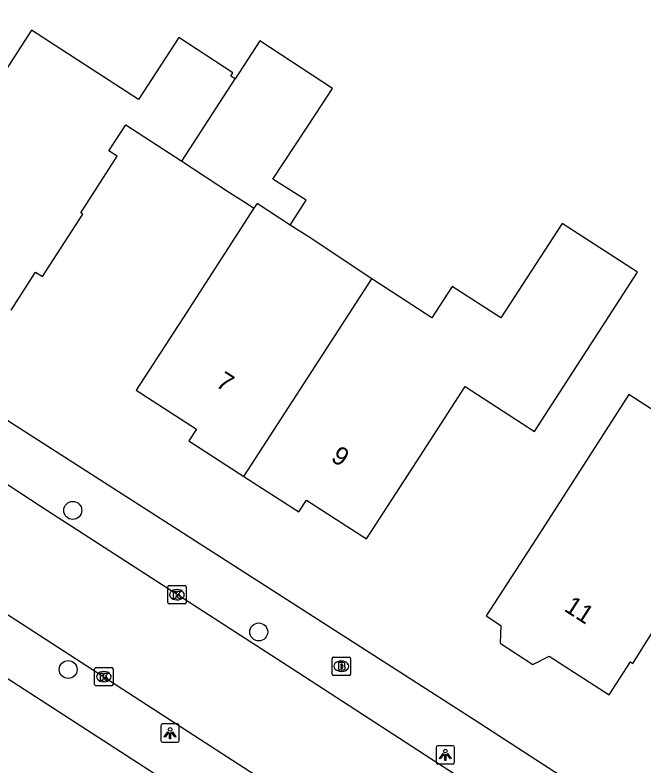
# Model space of a CAD drawing. Extents: x 161141 to 161601, y 381708 to 382245.
# Drawn here: x 161425.51 to 161459.73, y 382085.7 to 382126.58 of the extents above; entities that cross this region are included whole.
import ezdxf

# ---------------------------------------------------------------- set-up
doc = ezdxf.new("R2010")
doc.units = 0
for name, color, linetype in [('IMGEO_Boom', 7, 'Continuous'), ('IMGEO_Brandkraan', 7, 'Continuous'), ('IMGEO_Kolk', 7, 'Continuous'), ('IMGEO_Lichtpunt', 7, 'Continuous'), ('IMGEO_Pand', 7, 'Continuous'), ('IMGEO_Pand_nummerreeks', 7, 'Continuous'), ('IMGEO_Rijbaan_lokaal_open', 7, 'Continuous'), ('IMGEO_Voetpad_open', 7, 'Continuous')]:
    doc.layers.add(name, color=color, linetype=linetype)

msp = doc.modelspace()

# ---------------------------------------------------------------- linework, layer by layer
at = {"layer": 'IMGEO_Boom'}
for centre in [(161428.654, 382099.608), (161438.771, 382092.992), (161428.405, 382090.947)]:
    msp.add_circle(centre, 0.489, dxfattribs=at)
at = {"layer": 'IMGEO_Brandkraan'}
for p, q in [((161442.841, 382091.627), (161443.693, 382091.627)), ((161442.766, 382090.701), (161442.766, 382091.553)), ((161443.254, 382091.407), (161443.279, 382091.407)), ((161443.767, 382091.553), (161443.767, 382090.701)), ((161443.277, 382090.847), (161443.252, 382090.847)), ((161443.693, 382090.627), (161442.841, 382090.627))]:
    msp.add_line(p, q, dxfattribs=at)
for points in [[(161442.841, 382091.627), (161443.693, 382091.627)], [(161442.766, 382090.701), (161442.766, 382091.553)], [(161443.114, 382091.327), (161443.114, 382090.927), (161443.327, 382090.927)], [(161443.345, 382091.327), (161443.114, 382091.327)], [(161443.293, 382091.246), (161443.239, 382091.246), (161443.239, 382091.17)], [(161443.767, 382091.553), (161443.767, 382090.701)], [(161443.239, 382091.17), (161443.292, 382091.17)], [(161443.301, 382091.094), (161443.239, 382091.094), (161443.239, 382091.013)], [(161443.239, 382091.013), (161443.301, 382091.013)], [(161443.693, 382090.627), (161442.841, 382090.627)]]:
    msp.add_lwpolyline(points, dxfattribs=at)
for centre, radius, start, end in [((161442.843, 382091.551), 0.0765, 91.552, 178.448), ((161442.843, 382091.551), 0.0765, 91.552, 178.448), ((161443.691, 382091.551), 0.0765, 1.552, 88.448), ((161443.691, 382091.551), 0.0765, 1.552, 88.448), ((161443.294, 382091.208), 0.0379, 267.8285, 90.9355), ((161443.349, 382091.182), 0.145, 59.4692, 91.5367), ((161443.374, 382091.229), 0.0922, 285.5137, 58.1501), ((161443.302, 382091.053), 0.0404, 269.8759, 90.5077), ((161443.333, 382091.178), 0.251, 268.6676, 293.5347), ((161443.379, 382091.037), 0.105, 301.3115, 78.989), ((161442.843, 382090.703), 0.0765, 181.552, 268.448), ((161442.843, 382090.703), 0.0765, 181.552, 268.448), ((161443.691, 382090.703), 0.0765, 271.552, 358.448), ((161443.691, 382090.703), 0.0765, 271.552, 358.448)]:
    msp.add_arc(centre, radius, start, end, dxfattribs=at)
for centre, major_axis, ratio, start_param, end_param in [((161443.253, 382091.127), (-0.387, 0.002), 0.722429, 4.712389, 7.853982), ((161443.278, 382091.127), (-0.39, 0.002), 0.717154, 1.570796, 4.712389)]:
    msp.add_ellipse(centre, major_axis=major_axis, ratio=ratio, start_param=start_param, end_param=end_param, dxfattribs=at)
at = {"layer": 'IMGEO_Kolk'}
for p, q in [((161433.819, 382094.594), (161433.819, 382095.446)), ((161433.894, 382095.52), (161434.746, 382095.52)), ((161434.307, 382095.3), (161434.332, 382095.3)), ((161434.82, 382095.446), (161434.82, 382094.594)), ((161434.746, 382094.52), (161433.894, 382094.52)), ((161434.33, 382094.74), (161434.305, 382094.74)), ((161429.846, 382090.131), (161429.846, 382090.983)), ((161429.921, 382091.057), (161430.773, 382091.057)), ((161430.334, 382090.837), (161430.359, 382090.837)), ((161430.847, 382090.983), (161430.847, 382090.131)), ((161430.773, 382090.057), (161429.921, 382090.057)), ((161430.357, 382090.277), (161430.332, 382090.277))]:
    msp.add_line(p, q, dxfattribs=at)
for points in [[(161433.819, 382094.594), (161433.819, 382095.446)], [(161433.894, 382095.52), (161434.746, 382095.52)], [(161434.82, 382095.446), (161434.82, 382094.594)], [(161434.14, 382095.22), (161434.263, 382095.22), (161434.263, 382095.069), (161434.393, 382095.22), (161434.557, 382095.22), (161434.411, 382095.069), (161434.564, 382094.82), (161434.412, 382094.82), (161434.327, 382094.984), (161434.263, 382094.917), (161434.263, 382094.82), (161434.14, 382094.82), (161434.14, 382095.22)], [(161434.746, 382094.52), (161433.894, 382094.52)], [(161429.846, 382090.131), (161429.846, 382090.983)], [(161429.921, 382091.057), (161430.773, 382091.057)], [(161430.847, 382090.983), (161430.847, 382090.131)], [(161430.167, 382090.757), (161430.29, 382090.757), (161430.29, 382090.606), (161430.42, 382090.757), (161430.584, 382090.757), (161430.438, 382090.606), (161430.591, 382090.357), (161430.439, 382090.357), (161430.354, 382090.521), (161430.29, 382090.454), (161430.29, 382090.357), (161430.167, 382090.357), (161430.167, 382090.757)], [(161430.773, 382090.057), (161429.921, 382090.057)]]:
    msp.add_lwpolyline(points, dxfattribs=at)
for centre, start, end in [((161433.896, 382095.444), 91.552, 178.448), ((161433.896, 382095.444), 91.552, 178.448), ((161434.744, 382095.444), 1.552, 88.448), ((161434.744, 382095.444), 1.552, 88.448), ((161433.896, 382094.596), 181.552, 268.448), ((161433.896, 382094.596), 181.552, 268.448), ((161434.744, 382094.596), 271.552, 358.448), ((161434.744, 382094.596), 271.552, 358.448), ((161429.923, 382090.981), 91.552, 178.448), ((161429.923, 382090.981), 91.552, 178.448), ((161430.771, 382090.981), 1.552, 88.448), ((161430.771, 382090.981), 1.552, 88.448), ((161429.923, 382090.133), 181.552, 268.448), ((161429.923, 382090.133), 181.552, 268.448), ((161430.771, 382090.133), 271.552, 358.448), ((161430.771, 382090.133), 271.552, 358.448)]:
    msp.add_arc(centre, 0.0765, start, end, dxfattribs=at)
for centre, major_axis, ratio, start_param, end_param in [((161434.306, 382095.02), (-0.387, 0.002), 0.722429, 4.712389, 7.853982), ((161434.331, 382095.02), (-0.39, 0.002), 0.717154, 1.570796, 4.712389), ((161430.333, 382090.557), (-0.387, 0.002), 0.722429, 4.712389, 7.853982), ((161430.358, 382090.557), (-0.39, 0.002), 0.717154, 1.570796, 4.712389)]:
    msp.add_ellipse(centre, major_axis=major_axis, ratio=ratio, start_param=start_param, end_param=end_param, dxfattribs=at)
at = {"layer": 'IMGEO_Lichtpunt'}
for p, q in [((161434.35, 382087.983), (161433.542, 382087.983)), ((161434.35, 382087.983), (161433.542, 382087.983)), ((161433.448, 382087.888), (161433.448, 382087.081)), ((161433.448, 382087.888), (161433.448, 382087.081)), ((161434.444, 382087.081), (161434.444, 382087.888)), ((161434.444, 382087.081), (161434.444, 382087.888)), ((161433.542, 382086.987), (161434.35, 382086.987)), ((161433.542, 382086.987), (161434.35, 382086.987)), ((161448.424, 382086.706), (161448.424, 382085.899)), ((161448.424, 382086.706), (161448.424, 382085.899)), ((161449.326, 382086.801), (161448.518, 382086.801)), ((161449.326, 382086.801), (161448.518, 382086.801)), ((161449.42, 382085.899), (161449.42, 382086.706)), ((161449.42, 382085.899), (161449.42, 382086.706)), ((161448.518, 382085.805), (161449.326, 382085.805)), ((161448.518, 382085.805), (161449.326, 382085.805))]:
    msp.add_line(p, q, dxfattribs=at)
for points in [[(161433.822, 382087.552), (161433.861, 382087.524), (161433.673, 382087.262), (161433.635, 382087.289), (161433.822, 382087.552)], [(161434.034, 382087.524), (161434.072, 382087.551), (161434.259, 382087.289), (161434.22, 382087.261), (161434.034, 382087.524)], [(161433.924, 382087.504), (161433.971, 382087.504), (161433.971, 382087.182), (161433.924, 382087.182), (161433.924, 382087.504)], [(161448.798, 382086.37), (161448.837, 382086.342), (161448.649, 382086.08), (161448.611, 382086.107), (161448.798, 382086.37)], [(161448.9, 382086.322), (161448.947, 382086.322), (161448.947, 382086), (161448.9, 382086), (161448.9, 382086.322)], [(161449.01, 382086.342), (161449.048, 382086.369), (161449.235, 382086.107), (161449.196, 382086.079), (161449.01, 382086.342)]]:
    msp.add_lwpolyline(points, dxfattribs=at)
for centre in [(161433.947, 382087.686), (161448.923, 382086.504)]:
    msp.add_circle(centre, 0.0994, dxfattribs=at)
for centre, start, end in [((161433.542, 382087.888), 90, 180), ((161433.542, 382087.888), 90, 180), ((161434.35, 382087.888), 0, 90), ((161434.35, 382087.888), 0, 90), ((161433.542, 382087.081), 180, 270), ((161433.542, 382087.081), 180, 270), ((161434.35, 382087.081), 270, 0), ((161434.35, 382087.081), 270, 360), ((161448.518, 382086.706), 90, 180), ((161448.518, 382086.706), 90, 180), ((161449.326, 382086.706), 0, 90), ((161449.326, 382086.706), 0, 90), ((161448.518, 382085.899), 180, 270), ((161448.518, 382085.899), 180, 270), ((161449.326, 382085.899), 270, 0), ((161449.326, 382085.899), 270, 360)]:
    msp.add_arc(centre, 0.0946, start, end, dxfattribs=at)
at = {"layer": 'IMGEO_Pand'}
for points in [[(161437.484, 382123.096), (161437.252, 382123.247), (161437.371, 382123.43), (161434.42, 382125.349), (161432.231, 382121.978), (161426.411, 382125.757), (161424.649, 382123.042)], [(161440.486, 382115.143), (161441.356, 382116.489), (161439.546, 382117.641), (161441.891, 382121.207), (161442.785, 382122.568), (161438.836, 382125.164), (161437.484, 382123.096)], [(161434.584, 382118.612), (161437.484, 382123.096)], [(161425.295, 382110.508), (161426.632, 382112.574), (161427.002, 382112.335), (161429.204, 382115.738), (161429.086, 382115.814), (161431.074, 382118.885), (161430.619, 382119.179), (161431.54, 382120.593), (161434.584, 382118.612)], [(161434.584, 382118.612), (161437.189, 382116.917), (161438.153, 382116.29), (161438.514, 382116.055)], [(161440.486, 382115.143), (161438.679, 382116.311), (161438.514, 382116.055)], [(161438.514, 382116.055), (161434.82, 382110.347), (161432.104, 382106.149), (161435.385, 382104.027), (161434.978, 382103.397), (161437.966, 382101.463)], [(161437.966, 382101.463), (161440.952, 382099.531), (161441.366, 382100.171), (161444.638, 382098.054), (161447.354, 382102.252), (161450.002, 382106.345), (161453.77, 382103.907), (161459.379, 382112.577), (161455.281, 382115.234), (161451.951, 382110.085), (161449.302, 382111.799), (161448.197, 382110.09), (161444.922, 382112.208)], [(161444.922, 382112.208), (161441.455, 382114.516), (161440.486, 382115.143)], [(161437.966, 382101.463), (161444.922, 382112.208)], [(161472.701, 382105.54), (161469.366, 382107.698), (161465.469, 382101.675), (161458.914, 382105.916), (161456.737, 382102.518), (161453.857, 382098.067), (161451.141, 382093.869), (161451.95, 382093.346), (161451.901, 382092.38), (161453.687, 382091.225), (161454.573, 382091.678), (161457.833, 382089.569), (161458.989, 382091.357), (161459.126, 382091.268), (161464.273, 382099.499), (161467.455, 382097.44)]]:
    msp.add_lwpolyline(points, dxfattribs=at)
at = {"layer": 'IMGEO_Rijbaan_lokaal_open'}
for points in [[(161499.796, 382045.589), (161498.051, 382046.741), (161477.592, 382059.945), (161473.195, 382062.836), (161460.477, 382071.037), (161453.542, 382075.54), (161442.527, 382082.644), (161435.549, 382087.163), (161421.669, 382096.147), (161415.306, 382100.289), (161401.761, 382109.008), (161398.574, 382111.058), (161389.569, 382116.981), (161386.277, 382119.018), (161382.915, 382121.211), (161379.746, 382123.279), (161360.833, 382135.554)], [(161385.362, 382126.757), (161388.136, 382124.895), (161391.361, 382122.845), (161399.992, 382117.288), (161403.197, 382115.21), (161416.21, 382106.739), (161420.597, 382103.968), (161426.931, 382099.82), (161440.905, 382090.804), (161444.055, 382088.754), (161453.24, 382082.778), (161460.192, 382078.284), (161467.324, 382073.702), (161468.287, 382073.003), (161471.488, 382070.983), (161480.028, 382065.466), (161483.251, 382063.426), (161485.554, 382061.86), (161494.669, 382055.998), (161498.469, 382053.534), (161512.078, 382044.654), (161521.765, 382038.348), (161525.596, 382035.854)]]:
    msp.add_lwpolyline(points, dxfattribs=at)
at = {"layer": 'IMGEO_Voetpad_open'}
for points in [[(161523.437, 382040.853), (161500, 382056.07), (161450.498, 382088.211), (161408.789, 382114.947), (161389.855, 382127.317), (161365.175, 382143.293), (161365.084, 382143.565)], [(161359.011, 382133.266), (161498.24, 382043.117)]]:
    msp.add_lwpolyline(points, dxfattribs=at)

# ---------------------------------------------------------------- texts
at = {"layer": 'IMGEO_Pand_nummerreeks'}
for s, rotation, p in [('7', 327.1466, (161436.374, 382106.392)), ('9', 327.1466, (161442.641, 382102.345)), ('11', 327.2769, (161455.327, 382094.175))]:
    msp.add_text(s, height=1, rotation=rotation, dxfattribs=at).set_placement(p)

doc.saveas('drawing.dxf')
